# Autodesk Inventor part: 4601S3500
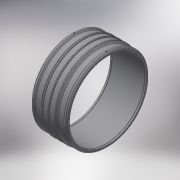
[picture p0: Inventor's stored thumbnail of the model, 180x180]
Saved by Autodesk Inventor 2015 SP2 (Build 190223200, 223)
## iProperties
Created: 2017-06
Part Number: 4601S3500
Material: Generic
Description: PLASSON SUPER LIGHTFIT 500 MM
Document SubType Name: Modeling
Designer: KIM
Mass: 9052.04 g
Surface Area: 10933.3 cm^2
Volume: 9052.04 cm^3
Density: 1 g/cm^3
Appearance: Default
Author: KIM
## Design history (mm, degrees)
derived "4601S3.ipt"
feature "Solid1::4601S3.ipt"
tag "TaggingFeature1"
body "Solid1"
other parameters: "d14" = 17.6296, "d19" = 3.52592, "d20" = 168 deg, "d22" = 544, "d24" = 527.68, "d25" = 135 deg, "d27" = 135 deg, "d29" = 272, "d35" = 15, "d39" = 0, "d40" = 4, "d41" = 14, "d42" = 0, "d43" = 135 deg, "d44" = 33, "d45" = 12, "d46" = 12, "d47" = 12, "d48" = 539, "d50" = 2.75, "d51" = 6, "d52" = 0, "A_" = 272, "d_2" = 12
